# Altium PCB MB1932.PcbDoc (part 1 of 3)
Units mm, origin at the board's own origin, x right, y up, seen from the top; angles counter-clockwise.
Board outline 70 x 82.5 mm, 2 copper layers (Top Layer, Bottom Layer), stack 1.543 mm thick; 185 components, 150 nets, 679 pads, 649 vias.
Unrouted connection lines stored in the file: 108.
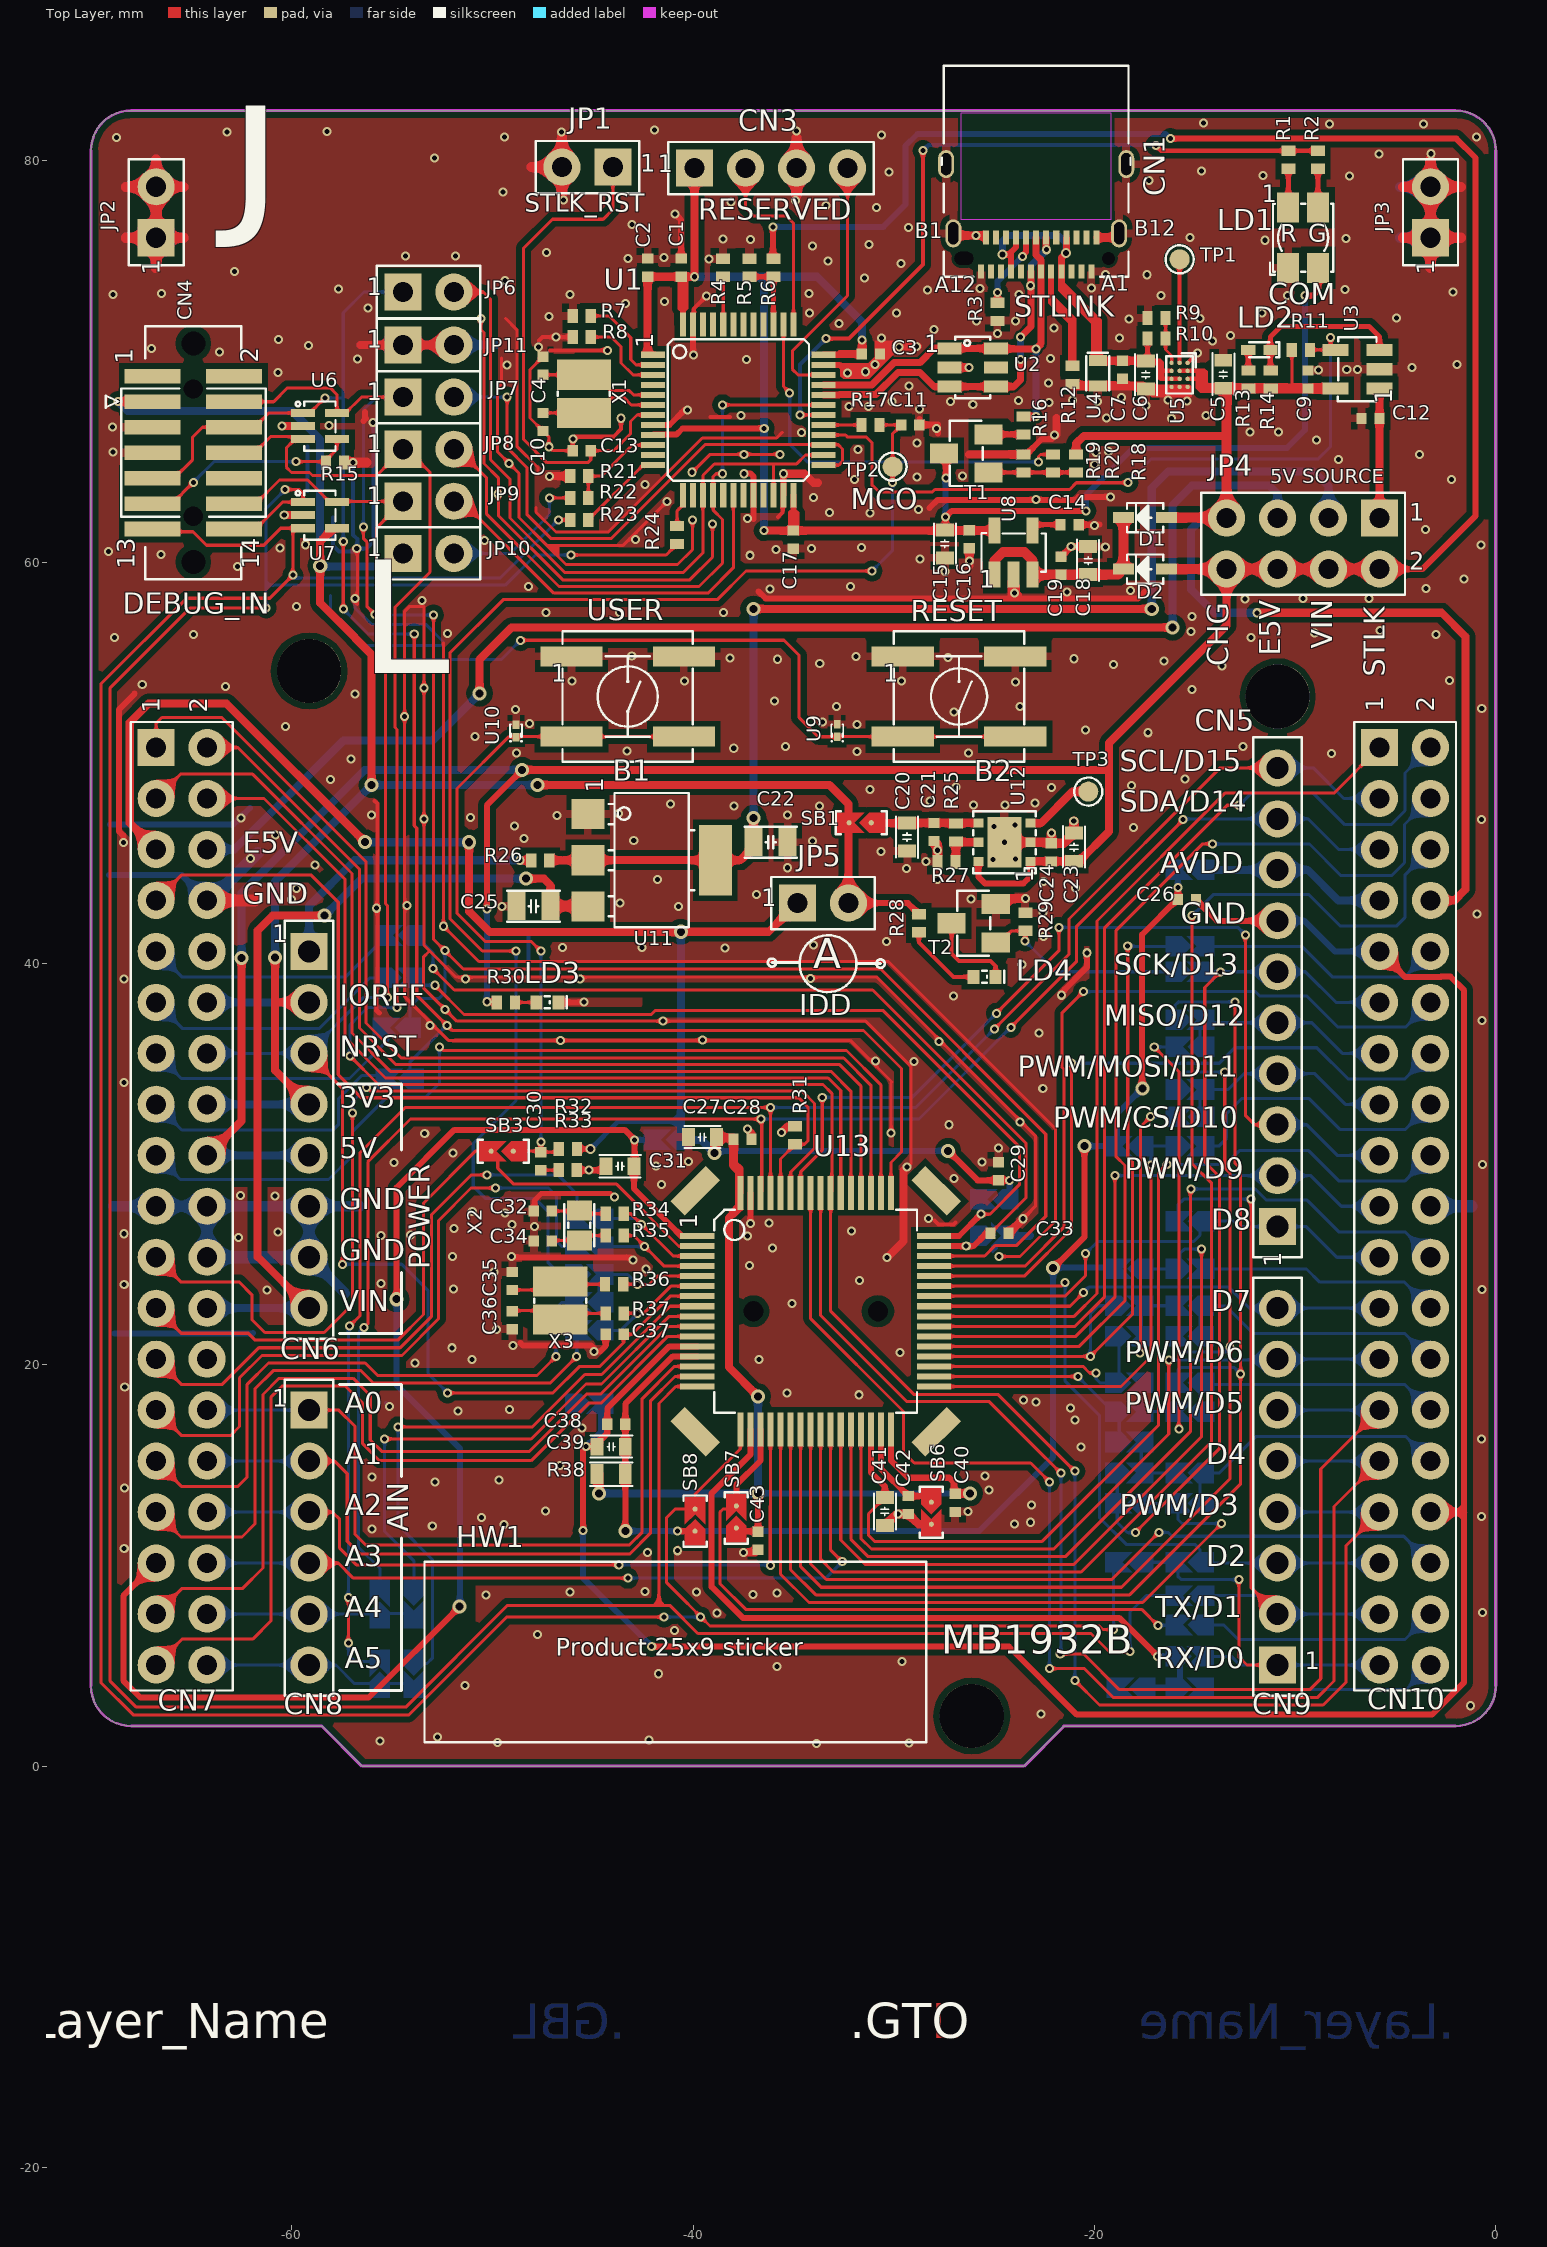
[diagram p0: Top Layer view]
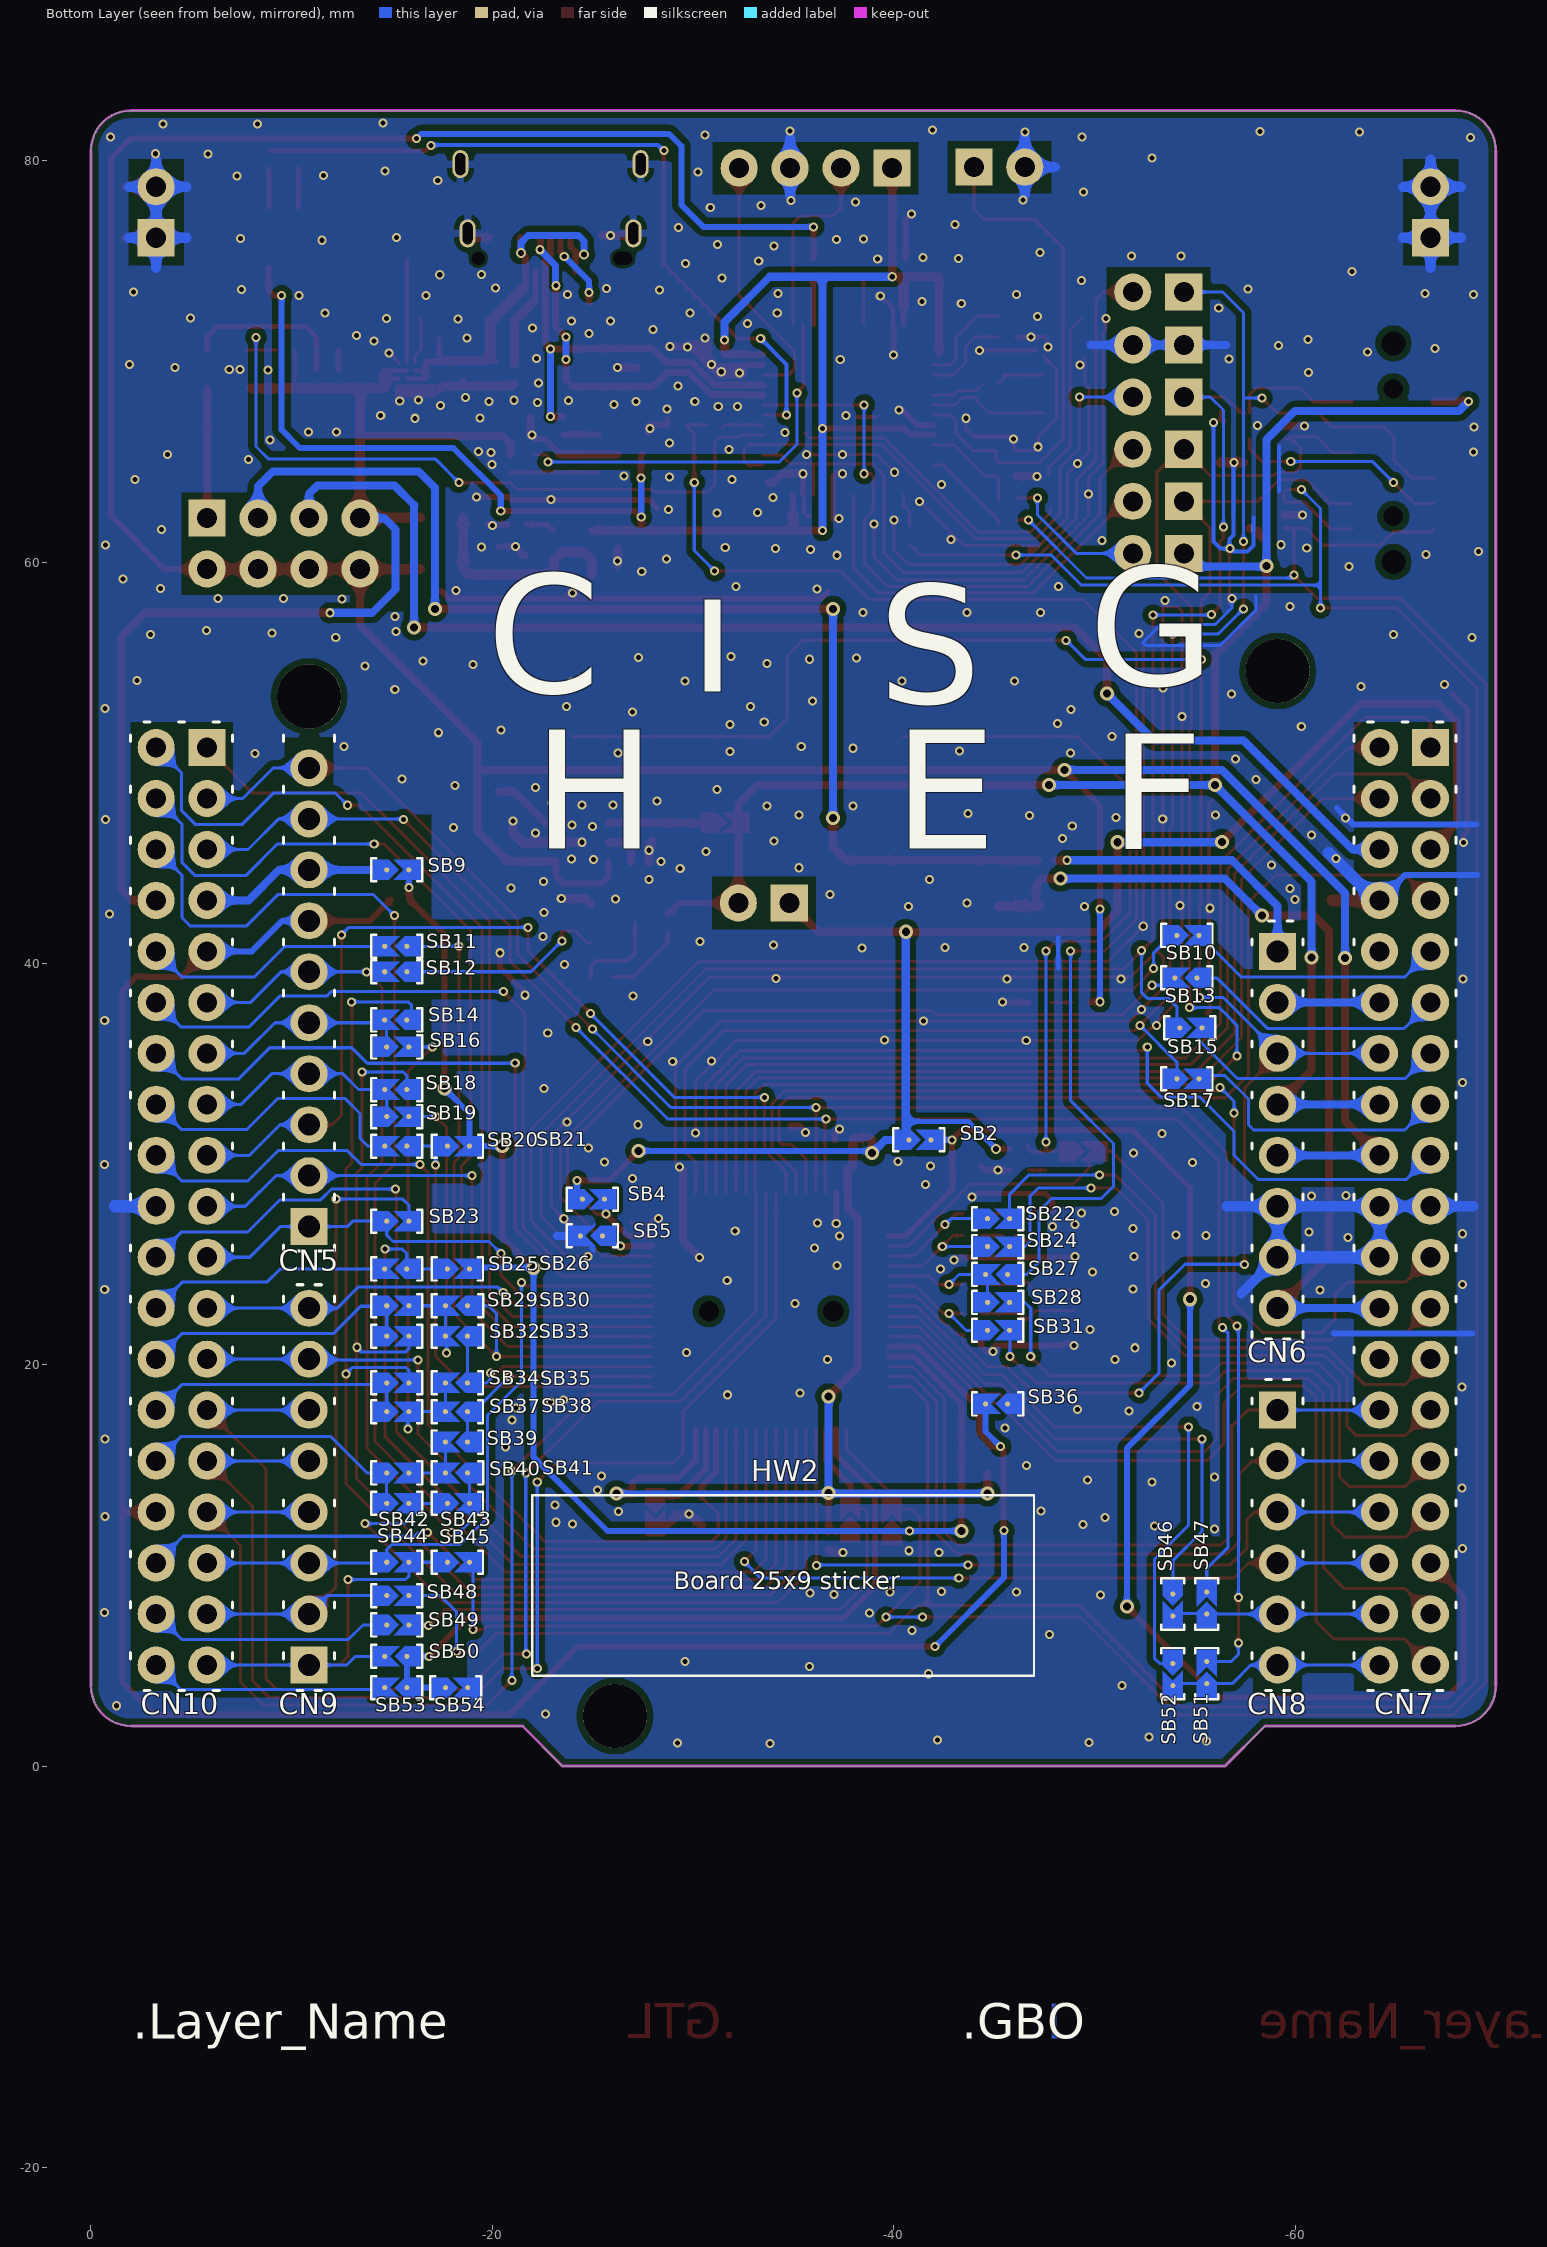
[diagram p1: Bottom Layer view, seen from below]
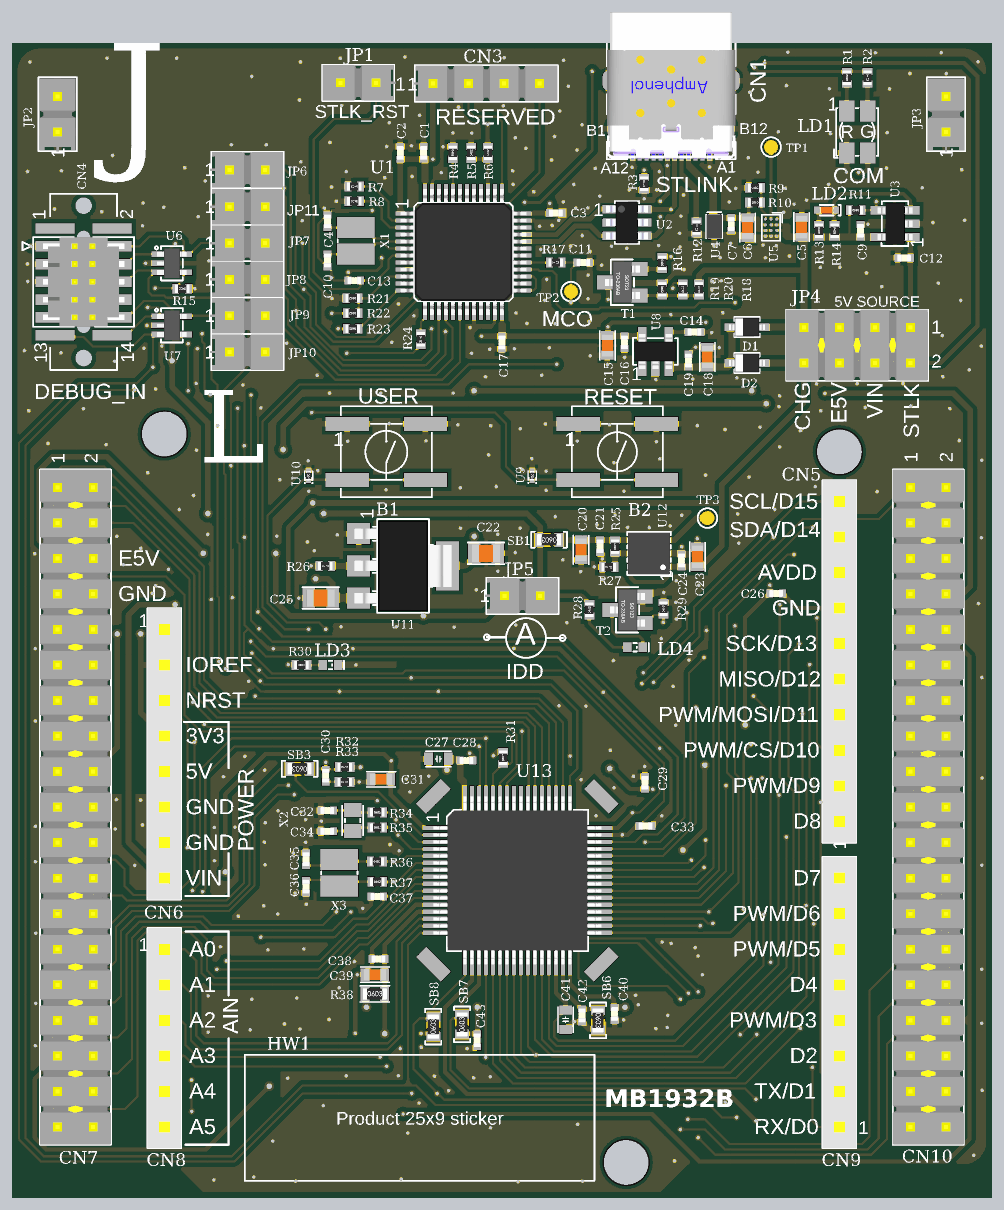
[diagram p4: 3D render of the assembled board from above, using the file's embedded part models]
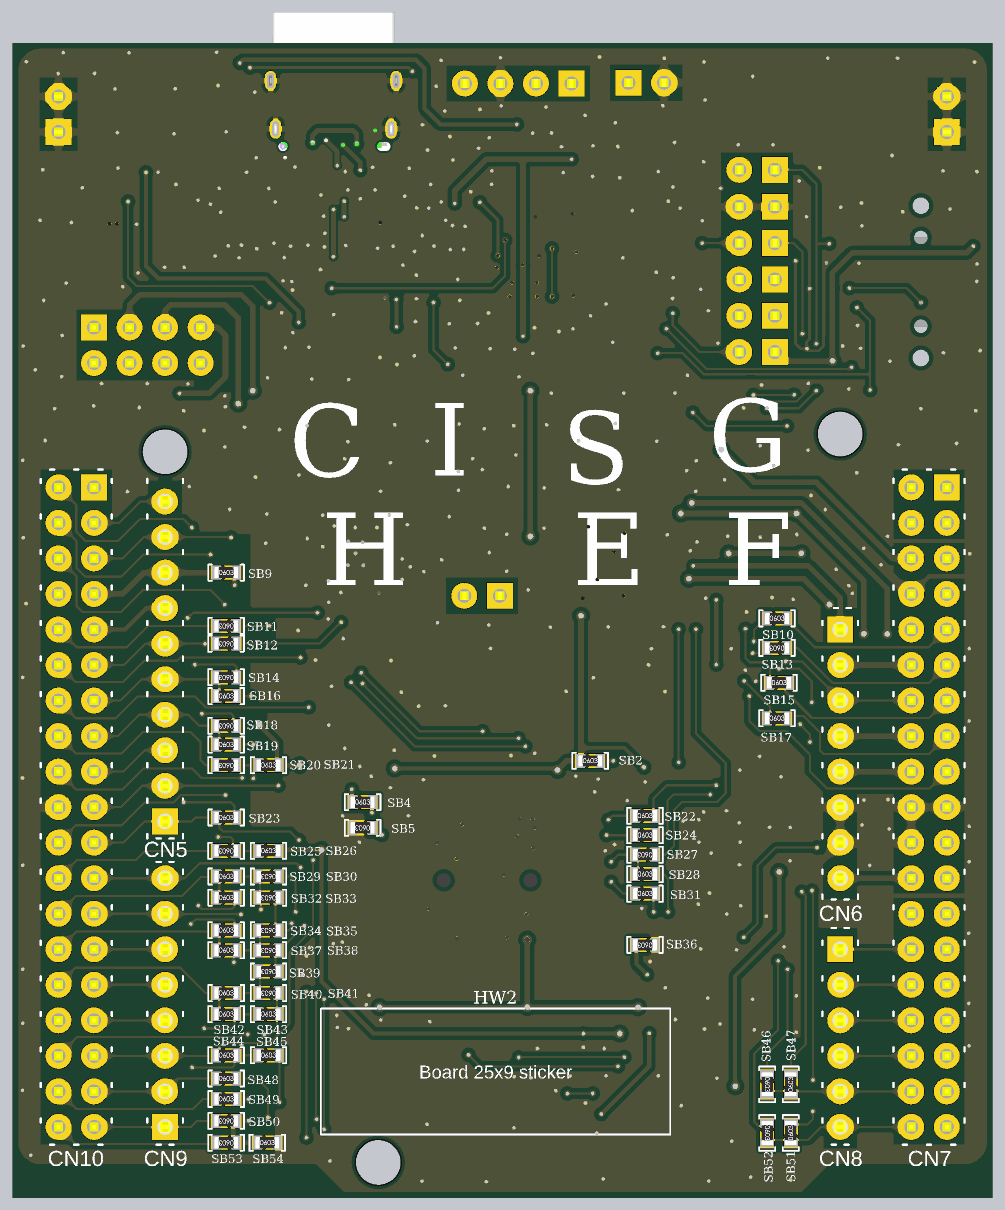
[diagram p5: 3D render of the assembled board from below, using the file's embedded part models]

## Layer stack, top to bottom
Top Solder: solder mask 0.015, Solder Resist, Dk 3.5
Top Layer: signal copper 0.035
Dielectric 1: core 1.4732, FR-4, Dk 4.2
Bottom Layer: signal copper 0.035
Bottom Solder: solder mask 0.015, Solder Resist, Dk 3.5

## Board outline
-68,2 -58.5,2 -56.5,0 -23.5,0 -21.5,2 -21.53,2 -2,2 ccw(c-2,4) 0,4 0,80.5 ccw(c-2,80.5) -2,82.5 -68,82.5 ccw(c-68,80.5) -70,80.5 -70,58 -70,57.974 -70,4 ccw(c-68,4)

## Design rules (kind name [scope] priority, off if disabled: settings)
Clearance USB [InDifferentialPair('STLK_USB')] p1: gap=0.127 ignorepadtopadclearanceinfootprint=FALSE
Clearance IN_CN1 [InComponent('CN1')] p2: gap=0.15 ignorepadtopadclearanceinfootprint=FALSE
Clearance AGND [InNet('AGND') vs InComponent('CN10')] p3: gap=0.14 ignorepadtopadclearanceinfootprint=TRUE
Clearance Polygon [InPolygon] p4: gap=0.3 ignorepadtopadclearanceinfootprint=FALSE
Clearance VIA&VIA [IsVia vs IsVia] p5: gap=0.2 ignorepadtopadclearanceinfootprint=FALSE
Clearance X3 [(HasFootprint('CRY_NX1612SA_4P'))] p6 off: gap=0.127 ignorepadtopadclearanceinfootprint=FALSE
Clearance SB [(HasFootprint('SOLDER-BRIDGE_R0603-0R'))] p7: gap=0.152 ignorepadtopadclearanceinfootprint=FALSE
Clearance U2 [(ObjectKind = 'Pad') And (Component = 'U2') vs (ObjectKind = 'Pad') And (Component = 'U2')] p8 off: gap=0.198 ignorepadtopadclearanceinfootprint=FALSE except(0: Arc-Hole Track-Hole SMDPad-Hole THPad-Hole Via-Hole Fill-Hole Poly-Hole Region-Hole Text-Hole)
Clearance U7 [(ObjectKind = 'Pad') And (Component = 'U7') vs (ObjectKind = 'Pad') And (Component = 'U7')] p9 off: gap=0.198 ignorepadtopadclearanceinfootprint=FALSE except(0: Arc-Hole Track-Hole SMDPad-Hole THPad-Hole Via-Hole Fill-Hole Poly-Hole Region-Hole Text-Hole)
Clearance [All] p10: gap=0.178 ignorepadtopadclearanceinfootprint=FALSE
ComponentClearance [All] p1: gap=0.2 collisioncheckmode=3 verticalgap=0 showdistances=FALSE
DiffPairsRouting [All] p1: maxlimit=0.508 minlimit=0.127 mostfreqgap=0.254 toplayer_minwidth=0.127 toplayer_maxwidth=0.381 toplayer_prefwidth=0.178 bottomlayer_minwidth=0.127 bottomlayer_maxwidth=0.381 bottomlayer_prefwidth=0.178 maxuncoupledlength=12.7
HoleSize [All] p1: absolutevalues=TRUE maxlimit=3.81 minlimit=0.025 maxpercent=80.000 minpercent=20.000
MaxMinImpedance "Schematic Impedance Constraint_2" [InNet('STLK_USB_P')] p1: minimum=85.00 maximum=95.00
MaxMinImpedance "Schematic Impedance Constraint_1" [InNet('STLK_USB_N')] p2: minimum=85.00 maximum=95.00
MinimumSolderMaskSliver [All] p1: minsoldermaskwidth=0
PlaneConnect [All] p1: planeconnectstyle=Relief reliefexpansion=0.508 reliefentries=4 reliefconductorwidth=0.4 reliefairgap=0.254
PolygonConnect VIA [IsVia] p1: connectstyle=Direct reliefconductorwidth=0.254 reliefentries=4 polygonreliefangle="90 Angle" airgapwidth=0.254
PolygonConnect [All] p2: connectstyle=Relief reliefconductorwidth=0.4 reliefentries=4 polygonreliefangle="90 Angle" airgapwidth=0.254
RoutingVias [All] p1: holewidth=0.203 width=0.381 viastyle="Through Hole" minholewidth=0.203 minwidth=0.381 maxholewidth=0.711 maxwidth=1.27
SilkToSilkClearance [All] p1: silktosilkclearance=0
SilkToSolderMaskClearance [IsPad] p1: minsilkscreentomaskgap=0.013 clearancetoexposedcopper=TRUE
SolderMaskExpansion [All] p1: expansion=0.102 istentingtop=FALSE
UnRoutedNet [All] p1: checkbadconnections=TRUE
Width [All] p1: maxlimit=0.762 minlimit=0.127 preferedwidth=0.203
22 further rules are at their usual default settings.

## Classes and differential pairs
net class PF[0..7]: PF0 PF1 PF4 PF5 PF6 PF7
component class U_STLINK_V2EC: C1 C2 C3 C4 C5 C6 C7 C9 C10 C11 C12 C13 C14 C15 C16 C17 C18 C19 CN1 CN3 CN4 D1 D2 JP1 JP6 JP7 JP8 JP9 JP10 JP11 LD1 LD2 R1 R2 R3 R4 R5 R6 R7 R8 R9 R10 R11 R12 R13 R14 R15 R16 R17 R18 R19 R20 R21 R22 R23 R24 T1 TP1 TP2 U1 U2 U3 U4 U5 U6 U7 U8 X1
net class PC[0..15]: PC0 PC1 PC2 PC3 PC4 PC5 PC6 PC7 PC8 PC9 PC10 PC11 PC12 PC13 PC14 PC15
net class PB[0..15]: PB0 PB1 PB2 PB3 PB4 PB5 PB6 PB7 PB8 PB9 PB10 PB11 PB12 PB13 PB14 PB15
net class PA[0..15]: PA0 PA1 PA2 PA3 PA4 PA5 PA6 PA7 PA8 PA9 PA10 PA11 PA12 PA13 PA14 PA15
component class U_Arduino_Morpho_connectors: C26 CN5 CN6 CN7 CN8 CN9 CN10 JP2 JP3 LD4 R26 R28 R29 SB9 SB12 SB14 SB15 SB16 SB17 SB18 SB19 SB22 SB23 SB24 SB28 SB29 SB31 SB32 SB34 SB37 SB40 SB41 SB42 SB43 SB44 SB46 SB47 SB51 SB52 T2
component class U_STM32_microcontroller_IOs: B1 B2 C27 C28 C29 C30 C31 C32 C33 C34 C35 C36 C37 C38 C39 C40 C41 C42 C43 HW6 HW7 HW8 HW9 R31 R32 R33 R34 R35 R36 R37 R38 SB2 SB3 SB4 SB5 SB6 SB7 SB8 SB10 SB11 SB13 SB20 SB21 SB25 SB26 SB27 SB30 SB33 SB35 SB36 SB38 SB39 SB45 SB48 SB49 SB50 SB53 SB54 U9 U10 U13 X2 X3
component class Power: C20 C21 C22 C23 C24 C25 HW12 HW13 JP4 JP5 LD3 R25 R27 R30 SB1 TP3 U11 U12
component class HW_Mechanical_Parts: HW1 HW2
differential pair STLK_USB: +STLK_USB_P -STLK_USB_N

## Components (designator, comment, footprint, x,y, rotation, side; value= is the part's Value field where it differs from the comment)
B1 "SW_BLUE_KSC721JLFS" SWI_C&K_KSC721JLFS_BLUE -43.255,53.3 r0 top locked value=KSC721JLFS
B2 "SW_BLACK_KSC321JLFS" SWI_C&K_KSC321JLFS_BLACK -26.745,53.3 r0 top locked value=KSC321JLFS
C1 "Capacitor" C0402 -40.588,74.672 r90 top value=100nF
C2 "Capacitor" C0402 -42.259,74.672 r90 top value=100nF
C3 "Capacitor" C0402 -31.137,70.37 r0 top value=100nF
C4 "Capacitor" C0402 -47.473,69.782 r270 top value=10pF
C5 "Capacitor" C0603 -13.575,69.357 r270 top value=10uF
C6 "Capacitor" C0603 -17.432,69.325 r270 top value=100nF
C7 "Capacitor" C0402 -18.601,69.581 r270 top value=100pF
C9 "Capacitor" C0402 -9.355,69.098 r270 top value=100nF
C10 "Capacitor" C0402 -47.473,66.982 r270 top value=10pF
C11 "Capacitor" C0402 -29.175,66.833 r180 top value=20pF
C12 "Capacitor" C0402 -6.241,67.158 r0 top value=100nF
C13 "Capacitor" C0402 -45.546,65.548 r0 top value=100nF
C14 "Capacitor" C0402 -21.232,61.862 r180 top value=10nF
C15 "Capacitor" C0603 -27.452,60.905 r90 top value=1uF
C16 "Capacitor" C0402 -26.232,61.133 r90 top value=100nF
C17 "Capacitor" C0402 -35.001,61.117 r270 top value=100nF
C18 "Capacitor" C0603 -20.311,60.073 r270 top value=1uF
C19 "Capacitor" C0402 -21.657,59.819 r270 top value=100nF
C20 "Capacitor" C0603 -29.335,46.297 r90 top value=1uF
C21 "Capacitor" C0402 -27.985,46.549 r90 top value=100nF
C22 "Capacitor" C0805 -36.131,46.043 r180 top value=10uF
C23 "Capacitor" C0603 -21.018,45.793 r270 top value=1uF
C24 "Capacitor" C0402 -22.148,45.534 r270 top value=100nF
C25 "Capacitor" C0805 -47.948,42.853 r0 top value=10uF
C26 "Capacitor" C0402 -15.391,43.181 r180 top value=100nF
C27 "Capacitor" C0603_H0P8 -39.532,31.343 r0 top value=4.7uF
C28 "Capacitor" C0402 -37.533,31.24 r180 top value=100nF
C29 "Capacitor" C0402 -24.777,29.643 r270 top value=100nF
C30 "Capacitor" C0402 -47.591,30.147 r90 top value=100nF
C31 "Capacitor" C0603 -43.64,29.893 r180 top value=1uF
C32 "Capacitor" C0402 -47.485,27.66 r0 top value=8.2pF
C33 "Capacitor" C0402 -24.73,26.55 r0 top value=2.2uF
C34 "Capacitor" C0402 -47.485,26.173 r0 top value=8.2pF
C35 "Capacitor" C0402 -49.004,24.18 r270 top value=10pF
C36 "Capacitor" C0402 -49.003,22.217 r90 top value=10pF
C37 "Capacitor" C0402 -43.901,21.517 r0 top value=100nF
C38 "Capacitor" C0402 -43.822,17.037 r0 top value=100nF
C39 "Capacitor" C0603 -44.076,15.919 r180 top value=1uF
C40 "Capacitor" C0402 -26.938,13.119 r90 top value=100nF
C41 "Capacitor" C0603_H0P8 -30.438,12.693 r270 top value=4.7uF
C42 "Capacitor" C0402 -29.271,13.01 r270 top value=2.2uF
C43 "Capacitor" C0402 -36.76,11.233 r90 top value=100nF
CN1 "USB_TYPE_C_Receptacle" CON_USB-TYPEC_AMPHENOL_12401826E412A -22.9,75.131 r180 top locked value=USB_C_12401826E412A
CN3 "Header 4x1" CON_SAMTEC_TSW-104-07-G-S -36.11,79.63 r0 top
CN4 "Header 7x2" CON_STDC14_Receiver_MEDIUM_WITH_MIPI10_3D -64.896,65.449 r270 top locked value="Header 5x2"
CN5 "Socket 10x1" CON_SAMTEC_SSW-110-01-X-S -10.87,38.314 r90 top locked
CN6 "Socket 8x1" CON_SAMTEC_SSW-108-01-X-S -59.13,31.71 r270 top locked
CN7 "Header 19x2" CON_SAMTEC_TSW-119-09-X-D -65.48,27.9 r270 top locked
CN8 "Socket 6x1" CON_SAMTEC_SSW-106-01-X-S -59.13,11.39 r270 top locked
CN9 "Socket 8x1" CON_SAMTEC_SSW-108-01-X-S -10.87,13.93 r90 top locked
CN10 "Header 19x2" CON_SAMTEC_TSW-119-09-X-D -4.52,27.9 r270 top locked
D1 "BAT60JFILM" DIO_SOD323 -17.474,62.215 r180 top
D2 "BAT60JFILM" DIO_SOD323 -17.474,59.65 r180 top
HW1 "STICKER_PRODUCT" STICKER_PRODUCT_25X9 -40.878,5.692 r0 top value="Sticker product"
HW2 "STICKER_BOARD" STICKER_BOARD_25X9 -34.492,8.999 r180 bottom value="Sticker board"
JP1 "Jumper_Header 2x1" CON_SAMTEC_TSW-102-07-G-S -45.263,79.68 r180 top value="Header 2x1"
JP2 "Jumper_Header 2x1" CON_SAMTEC_TSW-102-09-X-S -66.75,77.43 r90 top locked value="Header 2x1 16mm"
JP3 "Jumper_Header 2x1" CON_SAMTEC_TSW-102-09-X-S -3.25,77.43 r90 top locked value="Header 2x1 16mm"
JP4 "Jumper_Header 4x2 Fitted 1-2" CON_SAMTEC_TSW-104-07-X-D -9.6,60.92 r180 top locked value="Header 4x2"
JP5 "Jumper_Header 2x1 Fitted" CON_SAMTEC_TSW-102-07-G-S -33.528,43.008 r0 top locked value="Header 2x1"
JP6 "Jumper_Header 2x1 Fitted" CON_SAMTEC_TSW-102-07-G-S -53.185,73.458 r0 top value="Header 2x1"
JP7 "Jumper_Header 2x1 Fitted" CON_SAMTEC_TSW-102-07-G-S -53.185,68.217 r0 top value="Header 2x1"
JP8 "Jumper_Header 2x1 Fitted" CON_SAMTEC_TSW-102-07-G-S -53.185,65.621 r0 top value="Header 2x1"
JP9 "Jumper_Header 2x1 Fitted" CON_SAMTEC_TSW-102-07-G-S -53.185,63.028 r0 top value="Header 2x1"
JP10 "Jumper_Header 2x1 Fitted" CON_SAMTEC_TSW-102-07-G-S -53.185,60.432 r0 top value="Header 2x1"
JP11 "Jumper_Header 2x1 Fitted" CON_SAMTEC_TSW-102-07-G-S -53.185,70.818 r0 top value="Header 2x1"
LD1 "LED_BICOLOR" LED_BI-GR_WE-150141SV73110 -9.6,76.16 r0 top locked value="Green / Red"
LD2 "LED_red" LED_0402_KINGBRIGHT_KPHHS-1005SURCK_HYPER-RED_1A2K_H0P5 -11.782,70.571 r0 top value=RED
LD3 "LED_green" "LED_0402_EVERLIGHT_16-213SYGC/S530-E3-TR8 _YELLOW-GREEN_1A2K_H0P45" -47.256,38.06 r180 top locked value="Yellow Green"
LD4 "LED_green" "LED_0402_EVERLIGHT_16-213SYGC/S530-E3-TR8 _YELLOW-GREEN_1A2K_H0P45" -25.475,39.33 r180 top locked value="Yellow Green"
R1 "Resistor" R0402 -10.337,80.046 r90 top value=1K
R2 "Resistor" R0402 -8.863,80.046 r270 top value=330R
R3 "Resistor" R0402 -24.833,72.468 r270 top value=5K1
R4 "Resistor" R0402 -38.506,74.666 r270 top value=100K
R5 "Resistor" R0402 -37.186,74.666 r90 top value=10K
R6 "Resistor" R0402 -35.991,74.666 r90 top value=5K1
R7 "Resistor" R0402 -45.546,72.268 r180 top value=10K
R8 "Resistor" R0402 -45.546,71.212 r180 top value=10K
R9 "Resistor" R0402 -16.902,72.17 r0 top value=180K
R10 "Resistor" R0402 -16.902,71.129 r180 top value=680K
R11 "Resistor" R0402 -9.711,70.571 r180 top value=100K
R12 "Resistor" R0402 -21.087,69.328 r270 top value=5K1
R13 "Resistor" R0402 -12.327,69.098 r270 top value=1K
R14 "Resistor" R0402 -11.212,69.098 r270 top value=100K
R15 "Resistor" R0402 -57.843,64.955 r180 top value=100R
R16 "Resistor" R0402 -23.54,66.8 r270 top value=1K5
R17 "Resistor" R0402 -31.155,66.83 r0 top value=100R
R18 "Resistor" R0402 -20.911,64.91 r90 top value=10K
R19 "Resistor" R0402 -23.54,64.91 r270 top value=36K
R20 "Resistor" R0402 -22.064,64.91 r90 top value=100R
R21 "Resistor" R0402 -45.668,64.278 r180 top value=10K
R22 "Resistor" R0402 -45.668,63.202 r180 top value=10K
R23 "Resistor" R0402 -45.668,62.102 r180 top value=33R
R24 "Resistor" R0402 -40.79,61.35 r270 top value=0R
R25 "Resistor" R0402 -26.905,46.523 r90 top value=47K
R26 "Resistor" R0402 -47.615,45.139 r180 top value=1K
R27 "Resistor" R0402 -27.367,45.055 r0 top value=15K
R28 "Resistor" R0402 -28.742,42.002 r90 top value=680R
R29 "Resistor" R0402 -23.443,42.076 r90 top value=1M
R30 "Resistor" R0402 -49.326,38.06 r0 top value=680R
R31 "Resistor" R0402 -34.91,31.435 r90 top value=100K
R32 "Resistor" R0402 -46.235,30.76 r0 top value=5K1
R33 "Resistor" R0402 -46.24,29.697 r0 top value=100R
R34 "Resistor" R0402 -43.898,27.527 r0 top value=0R
R35 "Resistor" R0402 -43.898,26.441 r0 top value=0R
R36 "Resistor" R0402 -43.93,24.013 r0 top value=0R
R37 "Resistor" R0402 -43.898,22.565 r0 top value=0R
R38 "Resistor" R0603 -44.076,14.548 r0 top value=0R
SB1 "SB_ON" SOLDER-BRIDGE_R0603-0R -31.619,47.008 r180 top
SB2 "SB_ON" SOLDER-BRIDGE_R0603-0R -41.257,31.207 r180 bottom
SB3 "SB_ON" SOLDER-BRIDGE_R0603-0R -49.458,30.642 r180 top
SB4 "SB_ON" SOLDER-BRIDGE_R0603-0R -24.987,28.255 r180 bottom
SB5 "SB_ON" SOLDER-BRIDGE_R0603-0R -24.987,26.422 r0 bottom
SB6 "SB_ON" SOLDER-BRIDGE_R0603-0R -28.123,12.655 r270 top
SB7 "SB_ON" SOLDER-BRIDGE_R0603-0R -37.84,12.368 r90 top
SB8 "SB_OFF" SOLDER-BRIDGE_R0603-0R -39.9,12.21 r90 top
SB9 "SB_ON" SOLDER-BRIDGE_R0603-0R -15.239,44.664 r180 bottom
SB10 "SB_OFF" SOLDER-BRIDGE_R0603-0R -54.61,41.393 r180 bottom
SB11 "SB_OFF" SOLDER-BRIDGE_R0603-0R -15.239,40.854 r0 bottom
SB12 "SB_ON" SOLDER-BRIDGE_R0603-0R -15.24,39.584 r0 bottom
SB13 "SB_OFF" SOLDER-BRIDGE_R0603-0R -54.609,39.279 r0 bottom
SB14 "SB_ON" SOLDER-BRIDGE_R0603-0R -15.237,37.184 r0 bottom
SB15 "SB_OFF" SOLDER-BRIDGE_R0603-0R -54.758,36.79 r180 bottom
SB16 "SB_OFF" SOLDER-BRIDGE_R0603-0R -15.237,35.837 r180 bottom
SB17 "SB_OFF" SOLDER-BRIDGE_R0603-0R -54.609,34.25 r180 bottom
SB18 "SB_ON" SOLDER-BRIDGE_R0603-0R -15.239,33.717 r0 bottom
SB19 "SB_OFF" SOLDER-BRIDGE_R0603-0R -15.239,32.37 r180 bottom
SB20 "SB_ON" SOLDER-BRIDGE_R0603-0R -15.239,30.897 r0 bottom
SB21 "SB_OFF" SOLDER-BRIDGE_R0603-0R -18.261,30.897 r180 bottom
SB22 "SB_OFF" SOLDER-BRIDGE_R0603-0R -45.176,27.283 r180 bottom
SB23 "SB_OFF" SOLDER-BRIDGE_R0603-0R -15.239,27.156 r180 bottom
SB24 "SB_OFF" SOLDER-BRIDGE_R0603-0R -45.176,25.891 r180 bottom
SB25 "SB_ON" SOLDER-BRIDGE_R0603-0R -15.236,24.776 r0 bottom
SB26 "SB_OFF" SOLDER-BRIDGE_R0603-0R -18.259,24.776 r180 bottom
SB27 "SB_ON" SOLDER-BRIDGE_R0603-0R -45.176,24.5 r0 bottom
SB28 "SB_ON" SOLDER-BRIDGE_R0603-0R -45.176,23.108 r180 bottom
SB29 "SB_ON" SOLDER-BRIDGE_R0603-0R -15.241,22.942 r180 bottom
SB30 "SB_ON" SOLDER-BRIDGE_R0603-0R -18.263,22.942 r0 bottom
SB31 "SB_ON" SOLDER-BRIDGE_R0603-0R -45.176,21.717 r180 bottom
SB32 "SB_OFF" SOLDER-BRIDGE_R0603-0R -15.241,21.429 r180 bottom
SB33 "SB_OFF" SOLDER-BRIDGE_R0603-0R -18.263,21.429 r0 bottom
SB34 "SB_OFF" SOLDER-BRIDGE_R0603-0R -15.239,19.098 r180 bottom
SB35 "SB_ON" SOLDER-BRIDGE_R0603-0R -18.262,19.098 r0 bottom
SB36 "SB_ON" SOLDER-BRIDGE_R0603-0R -45.176,18.05 r0 bottom
SB37 "SB_ON" SOLDER-BRIDGE_R0603-0R -15.239,17.666 r180 bottom
SB38 "SB_OFF" SOLDER-BRIDGE_R0603-0R -18.262,17.666 r0 bottom
SB39 "SB_ON" SOLDER-BRIDGE_R0603-0R -18.262,16.153 r0 bottom
SB40 "SB_ON" SOLDER-BRIDGE_R0603-0R -15.241,14.61 r180 bottom
SB41 "SB_OFF" SOLDER-BRIDGE_R0603-0R -18.263,14.61 r0 bottom
SB42 "SB_OFF" SOLDER-BRIDGE_R0603-0R -15.238,13.097 r180 bottom
SB43 "SB_ON" SOLDER-BRIDGE_R0603-0R -18.261,13.097 r180 bottom
SB44 "SB_OFF" SOLDER-BRIDGE_R0603-0R -15.24,10.16 r180 bottom
SB45 "SB_OFF" SOLDER-BRIDGE_R0603-0R -18.263,10.16 r180 bottom
SB46 "SB_ON" SOLDER-BRIDGE_R0603-0R -53.909,8.083 r270 bottom
SB47 "SB_OFF" SOLDER-BRIDGE_R0603-0R -55.599,8.083 r90 bottom
SB48 "SB_OFF" SOLDER-BRIDGE_R0603-0R -15.239,8.499 r180 bottom
SB49 "SB_OFF" SOLDER-BRIDGE_R0603-0R -15.24,7.036 r180 bottom
SB50 "SB_OFF" SOLDER-BRIDGE_R0603-0R -15.24,5.474 r0 bottom
SB51 "SB_OFF" SOLDER-BRIDGE_R0603-0R -55.599,4.612 r90 bottom
SB52 "SB_ON" SOLDER-BRIDGE_R0603-0R -53.909,4.612 r270 bottom
SB53 "SB_OFF" SOLDER-BRIDGE_R0603-0R -15.24,3.912 r0 bottom
SB54 "SB_ON" SOLDER-BRIDGE_R0603-0R -18.173,3.912 r180 bottom
T1 "9013-SOT23" NPN_SOT23 -26.384,65.416 r90 top value="NPN SOT23"
T2 "BSN20" MOS_SOT23 -26.014,42.002 r90 top value=BSN20BK
TP1 "Test Point" TP_SMD_1MM -15.753,75.082 r180 top
TP2 "Test Point" TP_SMD_1MM -30.055,64.75 r90 top
TP3 "Test Point" TP_SMD_1MM -20.304,48.563 r180 top
U1 "STLINK-V2EC" ICC_LQFP48_7X7_P050 -37.743,67.58 r270 top locked value=STM32F103CBT6
U2 "USBLC6-2SC6" ESD_SOT23-6L -26.06,69.693 r270 top
U3 "STMPS2141STR" MOS_SOT23-5L -6.891,69.606 r90 top
U4 "ESD-TRANSIL" ESD_QFN1610_2N_1K_2A -19.825,69.408 r270 top value=ESDA25P35-1U1M
U5 "FPF3380UCX" ICC_WLCSP12_1P858x1P318_P040 -15.753,69.326 r270 top
U6 "ESDALC6V1W5" ESD_SOT323-5L -58.588,66.777 r270 top
U7 "ESDALC6V1W5" ESD_SOT323-5L -58.588,62.334 r270 top locked
U8 "LDK120M33R" REG_SOT23-5L -24.023,60.473 r0 top
U9 "ESD-TRANSIL" ESD_ST0201 -32.821,51.598 r90 top value=ESDALC6V1-1U2
U10 "ESD-TRANSIL" ESD_ST0201 -48.819,51.587 r90 top value=ESDALC6V1-1U2
U11 "LD1117S50TR" REG_SOT223-TAB -42.062,45.144 r270 top
U12 "LD39100PUR" ICC_DFN6-EPAD_3X3_P095 -24.48,46.038 r90 top
U13 "STM32_MCU_LQFP64" ICC_LQFP64_10X10_P050_SOCKET_YAMAICHI_IC149-064-069-B5_NM -33.888,22.668 r270 top locked value=STM32U083RCT6
X1 "XTAL_2_PINS" CRY_NX3225GD_2P -45.439,68.382 r90 top value=8MHz
X2 "XTAL_2_PINS" CRY_NX2012SA_2P -45.665,26.947 r90 top value=32.768KHz
X3 "XTAL_2_PINS" CRY_NX3225GD_2P -46.615,23.2 r90 top value=8MHz

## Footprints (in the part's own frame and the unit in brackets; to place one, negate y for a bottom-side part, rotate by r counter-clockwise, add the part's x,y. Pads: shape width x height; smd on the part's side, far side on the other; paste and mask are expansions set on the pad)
C0402 [mm]
  rect 0.51x0.56 smd mask+0.05: 1(-0.45,0) 2(0.45,0)
  body extent -0.5,-0.3 0.5,0.3, height 0.4
C0603 [mm]
  rect 0.64x0.89 smd mask+0.05: 1(-0.7,0) 2(0.7,0)
  silkscreen extent -1.05,-0.55 1.02,0.55, body extent -0.9,-0.5 0.9,0.5, height 1.4
C0603_H0P8 [mm] "MCD-01540"
  rect 0.64x0.89 smd mask+0.05: 1(-0.7,0) 2(0.7,0)
  silkscreen extent -0.9,-0.55 0.9,0.55, body extent -0.9,-0.5 0.9,0.5, height 1
C0805 [mm]
  rect 0.9x1.4 smd mask+0.05: 1(-0.85,0) 2(0.85,0)
  silkscreen extent -1.3,-0.77 1.3,0.77, body extent -1.1,-0.7 1.1,0.7, height 1.35
CON_SAMTEC_SSW-106-01-X-S [mm] "MCD-02079"
  rect 1.85x1.85 / inner round 1.85 / far side rect 1.85x1.85 hole 1.1 mask+0.05: 1(-6.35,0)
  round 1.85 hole 1.1 mask+0.05: 2(-3.81,0) 3(-1.27,0) 4(1.27,0) 5(3.81,0) 6(6.35,0)
  silkscreen extent -7.88,-1.2 7.88,1.2, body extent -7.88,-1.21 7.88,1.21, height 8.51
CON_SAMTEC_SSW-108-01-X-S [mm] "MCD-01743"
  rect 1.85x1.85 / inner round 1.85 / far side rect 1.85x1.85 hole 1.1 mask+0.05: 1(-8.89,0)
  round 1.85 hole 1.1 mask+0.05: 2(-6.35,0) 3(-3.81,0) 4(-1.27,0) 5(1.27,0) 6(3.81,0) 7(6.35,0) 8(8.89,0)
  silkscreen extent -10.42,-1.2 10.42,1.2, body extent -10.42,-1.21 10.42,1.21, height 8.51
CON_SAMTEC_SSW-110-01-X-S [mm] "MCD-02080"
  rect 1.85x1.85 / inner round 1.85 / far side rect 1.85x1.85 hole 1.1 mask+0.05: 1(-11.43,0)
  round 1.85 hole 1.1 mask+0.05: 2(-8.89,0) 3(-6.35,0) 4(-3.81,0) 5(-1.27,0) 6(1.27,0) 7(3.81,0) 8(6.35,0) 9(8.89,0) 10(11.43,0)
  silkscreen extent -12.96,-1.2 12.96,1.2, body extent -12.96,-1.21 12.96,1.21, height 8.51
CON_SAMTEC_TSW-102-07-G-S [mm]
  rect 1.85x1.85 / inner round 1.85 / far side rect 1.85x1.85 hole 1 mask+0.05: 1(-1.27,0)
  round 1.85 hole 1 mask+0.05: 2(1.27,0)
  silkscreen extent -2.58,-1.3 2.58,1.3, body extent -2.67,-1.3 2.58,1.3, height 8.38
CON_SAMTEC_TSW-102-09-X-S [mm]
  rect 1.85x1.85 / inner round 1.85 / far side rect 1.85x1.85 hole 1 mask+0.05: 1(-1.27,0)
  round 1.85 hole 1 mask+0.05: 2(1.27,0)
  silkscreen extent -2.64,-1.37 2.64,1.37, body extent -2.67,-1.3 2.58,1.3, height 8.38
CON_SAMTEC_TSW-104-07-G-S [mm]
  rect 1.85x1.85 / inner round 1.85 / far side rect 1.85x1.85 hole 1 mask+0.05: 1(-3.81,0)
  round 1.85 hole 1 mask+0.05: 2(-1.27,0) 3(1.27,0) 4(3.81,0)
  silkscreen extent -5.12,-1.3 5.12,1.3, body extent -5.21,-1.37 5.18,1.37, height 8.38
CON_SAMTEC_TSW-104-07-X-D [mm]
  rect 1.85x1.85 / inner round 1.85 / far side rect 1.85x1.85 hole 1 mask+0.05: 1(-3.81,-1.27)
  round 1.85 hole 1 mask+0.05: 2(-3.81,1.27) 3(-1.27,-1.27) 4(-1.27,1.27) 5(1.27,-1.27) 6(1.27,1.27) 7(3.81,-1.27) 8(3.81,1.27)
  silkscreen extent -5.08,-2.54 5.08,2.54, body extent -5.08,-2.54 5.08,2.54, height 8.38
CON_SAMTEC_TSW-119-09-X-D [mm]
  rect 1.85x1.85 / inner round 1.85 / far side rect 1.85x1.85 hole 1 mask+0.05: 1(-22.86,-1.27)
  round 1.85 hole 1 mask+0.05: 2(-22.86,1.27) 3(-20.32,-1.27) 4(-20.32,1.27) 5(-17.78,-1.27) 6(-17.78,1.27) 7(-15.24,-1.27) 8(-15.24,1.27) 9(-12.7,-1.27) 10(-12.7,1.27) 11(-10.16,-1.27) 12(-10.16,1.27) 13(-7.62,-1.27) 14(-7.62,1.27) 15(-5.08,-1.27) 16(-5.08,1.27) 17(-2.54,-1.27) 18(-2.54,1.27) 19(0,-1.27) 20(0,1.27) 21(2.54,-1.27) 22(2.54,1.27) 23(5.08,-1.27) 24(5.08,1.27) 25(7.62,-1.27) 26(7.62,1.27) 27(10.16,-1.27) 28(10.16,1.27) 29(12.7,-1.27) 30(12.7,1.27) 31(15.24,-1.27) 32(15.24,1.27) 33(17.78,-1.27) 34(17.78,1.27) 35(20.32,-1.27) 36(20.32,1.27) 37(22.86,-1.27) 38(22.86,1.27)
  silkscreen extent -24.13,-2.54 24.13,2.54, body extent -24.13,-2.55 24.13,2.54, height 8.38
CON_STDC14_Receiver_MEDIUM_WITH_MIPI10_3D [mm] "compatible with FTSH-105-01-L-DV,-K and FTSH-107-01-L-DV,-K,-A,-P,-ES"
  round 0 hole 1.19 unplated mask+0.05: 0(-5.445,0) 0(5.445,0)
  round 0 hole 0.97 unplated mask+0.05: 0(-3.175,0) 0(3.175,0)
  rect 0.74x2.79 smd mask+0.05: 1(-3.81,-2.032) 2(-3.81,2.032) 3(-2.54,-2.032) 4(-2.54,2.032) 5(-1.27,-2.032) 6(-1.27,2.032) 7(0,-2.032) 8(0,2.032) 9(1.27,-2.032) 10(1.27,2.032) 11(2.54,-2.032) 12(2.54,2.032) 13(3.81,-2.032) 14(3.81,2.032)
  silkscreen extent -6.3,-4.38 6.3,3.6, body extent -6.3,-2.92 6.3,2.92, height 6.6
CON_USB-TYPEC_AMPHENOL_12401826E412A [mm] "MCD-03232"
  round 0 hole 0.65 unplated mask+0.05: 0(-3.6,0)
  round 0 hole 0.65 slot 0.95 at 0 deg unplated mask+0.05: 0(3.6,0)
  rect 0.3x0.7 smd mask+0.05: A1(-2.75,0.66) A2(-2.25,0.66) A3(-1.75,0.66) A4(-1.25,0.66) A5(-0.75,0.66) A6(-0.25,0.66) A7(0.25,0.66) A8(0.75,0.66) A9(1.25,0.66) A10(1.75,0.66) A11(2.25,0.66) A12(2.75,0.66) B1(2.5,-1.04) B2(2,-1.04) B3(1.5,-1.04) B4(1,-1.04) B5(0.5,-1.04) B6(0,-1.04) B7(-0.5,-1.04) B8(-1,-1.04) B9(-1.5,-1.04) B10(-2,-1.04) B11(-2.5,-1.04) B12(-3,-1.04)
  oval 0.8x1.4 hole 0.5 slot 1.1 at 90 deg mask+0.05: SH1(-4.13,-1.25) SH2(4.13,-1.25) SH3(-4.49,-4.7) SH4(4.49,-4.7)
  Top Layer keep-out region: -3.75,-7.24 3.75,-7.24 3.75,-1.95 -3.75,-1.95
  silkscreen extent -4.7,-9.59 4.7,0.91, body extent -4.6,-9.59 4.6,0.91, height 3.25
CRY_NX2012SA_2P [mm]
  rect 1x1.25 smd mask+0.05: 1(-0.75,0) 2(0.75,0)
  silkscreen extent -1.05,-0.75 1.05,0.75, body extent -1.05,-0.63 1.05,0.63, height 0.6
CRY_NX3225GD_2P [mm]
  rect 1.5x2.7 smd mask+0.05: 1(-0.95,0) 2(0.95,0)
  silkscreen extent -0.1,-1.3 0.1,1.3, body extent -1.65,-1.3 1.65,1.3, height 1
DIO_SOD323 [mm]
  rect 1.06x0.54 smd mask+0.05: 1(-1.07,0) 2(1.07,0)
  silkscreen extent -0.9,-0.72 0.9,0.72, body extent -1.3,-0.78 1.3,0.78, height 1.17
ESD_QFN1610_2N_1K_2A [mm] "DFN, 2-Leads, Body 1.60x1.00mm"
  rect 0.55x0.9 smd mask+0.05: 1(-0.625,0) 2(0.625,0)
  silkscreen extent -1.02,-0.58 0.85,0.58, body extent -0.85,-0.55 0.85,0.55, height 0.6
ESD_SOT23-6L [mm]
  rect 0.6x1.2 smd mask+0.05: 1(-0.95,-1.15) 2(0,-1.15) 3(0.95,-1.15) 4(0.95,1.15) 5(0,1.15) 6(-0.95,1.15)
  silkscreen extent -1.53,-0.87 1.53,0.87, body extent -1.52,-1.5 1.52,1.5, height 1.45
ESD_SOT323-5L [mm]
  rect 0.4x1.2 smd mask+0.05: 1(-0.65,-0.85) 2(0,-0.85) 3(0.65,-0.85) 4(0.65,0.85) 5(-0.65,0.85)
  silkscreen extent -1.22,-1.21 1.22,0.77, body extent -1.15,-1.05 1.15,1.05, height 1.1
ESD_ST0201 [mm]
  rect 0.425x0.33 smd mask+0.05: 1(-0.312,0) 2(0.312,0)
  silkscreen extent -0.55,-0.3 0.33,0.3, body extent -0.34,-0.18 0.34,0.18, height 0.34
ICC_DFN6-EPAD_3X3_P095 [mm]
  rect 0.45x0.5 smd mask+0.05: 1(-0.95,-1.3) 2(0,-1.3) 3(0.95,-1.3) 4(0.95,1.3) 5(0,1.3) 6(-0.95,1.3)
  rect 2.5x1.7 smd mask+0.05: EP(0,0)
  silkscreen extent -1.55,-1.55 1.55,1.55, body extent -1.55,-1.55 1.55,1.55, height 1
ICC_LQFP48_7X7_P050 [mm]
  rect 0.3x1.2 smd mask+0.05: 1(-2.75,-4.25) 2(-2.25,-4.25) 3(-1.75,-4.25) 4(-1.25,-4.25) 5(-0.75,-4.25) 6(-0.25,-4.25) 7(0.25,-4.25) 8(0.75,-4.25) 9(1.25,-4.25) 10(1.75,-4.25) 11(2.25,-4.25) 12(2.75,-4.25) 25(2.75,4.25) 26(2.25,4.25) 27(1.75,4.25) 28(1.25,4.25) 29(0.75,4.25) 30(0.25,4.25) 31(-0.25,4.25) 32(-0.75,4.25) 33(-1.25,4.25) 34(-1.75,4.25) 35(-2.25,4.25) 36(-2.75,4.25)
  rect 1.2x0.3 smd mask+0.05: 13(4.25,-2.75) 14(4.25,-2.25) 15(4.25,-1.75) 16(4.25,-1.25) 17(4.25,-0.75) 18(4.25,-0.25) 19(4.25,0.25) 20(4.25,0.75) 21(4.25,1.25) 22(4.25,1.75) 23(4.25,2.25) 24(4.25,2.75) 37(-4.25,2.75) 38(-4.25,2.25) 39(-4.25,1.75) 40(-4.25,1.25) 41(-4.25,0.75) 42(-4.25,0.25) 43(-4.25,-0.25) 44(-4.25,-0.75) 45(-4.25,-1.25) 46(-4.25,-1.75) 47(-4.25,-2.25) 48(-4.25,-2.75)
  silkscreen extent -3.52,-3.52 3.52,3.52, body extent -4.5,-4.5 4.5,4.5, height 1.6
ICC_LQFP64_10X10_P050_SOCKET_YAMAICHI_IC149-064-069-B5_NM [mm]
  rect 1x2.5 smd rot 135 mask+0.05: 0(-6,6) 0(6,-6)
  rect 1x2.5 smd rot 45 mask+0.05: 0(-6,-6) 0(6,6)
  round 0.5 hole 1 unplated mask+0.05: 0(0,3.1) 0(0,-3.1)
  rect 0.3x1.7 smd mask+0.05: 1(-3.75,-5.9) 2(-3.25,-5.9) 3(-2.75,-5.9) 4(-2.25,-5.9) 5(-1.75,-5.9) 6(-1.25,-5.9) 7(-0.75,-5.9) 8(-0.25,-5.9) 9(0.25,-5.9) 10(0.75,-5.9) 11(1.25,-5.9) 12(1.75,-5.9) 13(2.25,-5.9) 14(2.75,-5.9) 15(3.25,-5.9) 16(3.75,-5.9) 33(3.75,5.9) 34(3.25,5.9) 35(2.75,5.9) 36(2.25,5.9) 37(1.75,5.9) 38(1.25,5.9) 39(0.75,5.9) 40(0.25,5.9) 41(-0.25,5.9) 42(-0.75,5.9) 43(-1.25,5.9) 44(-1.75,5.9) 45(-2.25,5.9) 46(-2.75,5.9) 47(-3.25,5.9) 48(-3.75,5.9)
  rect 1.7x0.3 smd mask+0.05: 17(5.9,-3.75) 18(5.9,-3.25) 19(5.9,-2.75) 20(5.9,-2.25) 21(5.9,-1.75) 22(5.9,-1.25) 23(5.9,-0.75) 24(5.9,-0.25) 25(5.9,0.25) 26(5.9,0.75) 27(5.9,1.25) 28(5.9,1.75) 29(5.9,2.25) 30(5.9,2.75) 31(5.9,3.25) 32(5.9,3.75) 49(-5.9,3.75) 50(-5.9,3.25) 51(-5.9,2.75) 52(-5.9,2.25) 53(-5.9,1.75) 54(-5.9,1.25) 55(-5.9,0.75) 56(-5.9,0.25) 57(-5.9,-0.25) 58(-5.9,-0.75) 59(-5.9,-1.25) 60(-5.9,-1.75) 61(-5.9,-2.25) 62(-5.9,-2.75) 63(-5.9,-3.25) 64(-5.9,-3.75)
  silkscreen extent -5.05,-5.05 5.05,5.05, body extent -6,-6 6,6, height 1.6
ICC_WLCSP12_1P858x1P318_P040 [mm] "MCD-03166"
  round 0.215 smd paste+0 mask+0.04: A1(-0.6,0.4) A2(-0.2,0.4) A3(0.2,0.4) A4(0.6,0.4) B1(-0.6,0) B2(-0.2,0) B3(0.2,0) B4(0.6,0) C1(-0.6,-0.4) C2(-0.2,-0.4) C3(0.2,-0.4) C4(0.6,-0.4)
  silkscreen extent -1.07,-0.66 0.93,0.8, body extent -0.93,-0.66 0.93,0.66, height 0.62
"LED_0402_EVERLIGHT_16-213SYGC/S530-E3-TR8 _YELLOW-GREEN_1A2K_H0P45" [mm] "MCD-02330"
  rect 0.6x0.7 smd mask+0.05: 1(0.55,0) 2(-0.55,0)
  silkscreen extent -0.97,-0.3 0.13,0.3, body extent -0.55,-0.3 0.55,0.3, height 0.55
LED_0402_KINGBRIGHT_KPHHS-1005SURCK_HYPER-RED_1A2K_H0P5 [mm] "MCD-00708"
  rect 0.7x0.5 smd mask+0.05: 1(-0.55,0) 2(0.55,0)
  silkscreen extent -0.5,-0.38 1,0.38, body extent -0.5,-0.3 0.51,0.3, height 0.6
LED_BI-GR_WE-150141SV73110 [mm] "MCD-02631"
  rect 1.1x1.5 smd mask+0.05: 1(-0.75,1.5) 2(0.75,1.5) 3(-0.75,-1.5) 4(0.75,-1.5)
  silkscreen extent -1.65,-1.85 1.5,1.7, body extent -1.5,-1.85 1.5,1.85, height 2.1
MOS_SOT23 [mm]
  rect 1x1.4 smd mask+0.05: 1(-0.95,-1.1) 2(0.95,-1.1) 3(0,1.1)
  silkscreen extent -1.63,-0.82 1.63,0.82, body extent -1.56,-1.25 1.56,1.25, height 1.1
MOS_SOT23-5L [mm]
  rect 0.6x1.3 smd mask+0.05: 1(-0.95,-1.1) 2(0,-1.1) 3(0.95,-1.1) 4(0.95,1.1) 5(-0.95,1.1)
  silkscreen extent -1.6,-0.95 1.6,0.97, body extent -1.52,-1.25 1.52,1.25, height 1.45
NPN_SOT23 [mm]
  rect 1x1.4 smd mask+0.05: 1(-0.95,-1.1) 2(0.95,-1.1) 3(0,1.1)
  silkscreen extent -1.63,-0.82 1.63,0.82, body extent -1.56,-1.25 1.56,1.25, height 1.1
R0402 [mm]
  rect 0.51x0.7 smd mask+0.05: 1(-0.45,0) 2(0.45,0)
  body extent -0.52,-0.3 0.52,0.3, height 0.4
R0603 [mm]
  rect 0.64x1 smd mask+0.05: 1(-0.7,0) 2(0.7,0)
  silkscreen extent -1.05,-0.58 1.05,0.58, body extent -0.9,-0.5 0.9,0.5, height 0.56
REG_SOT23-5L [mm]
  rect 0.6x1.3 smd mask+0.05: 1(-0.95,-1.1) 2(0,-1.1) 3(0.95,-1.1) 4(0.95,1.1) 5(-0.95,1.1)
  silkscreen extent -1.6,-0.95 1.6,0.97, body extent -1.52,-1.25 1.52,1.25, height 1.1
REG_SOT223-TAB [mm]
  rect 1.5x1.65 smd mask+0.05: 1(-2.3,-3.175) 2(0,-3.175) 3(2.3,-3.175)
  rect 3.5x1.65 smd mask+0.05: 4(0,3.175)
  silkscreen extent -3.35,-2.15 3.35,2.12, body extent -3.35,-3.48 3.35,3.48, height 1.8
SOLDER-BRIDGE_R0603-0R [mil]
  round 10 smd paste-393.7: 1(-19.68,0) 2(23.62,0)
  Top Layer region: -5.91,19.69 13.78,0 -5.91,-19.68 47.24,-19.68 47.24,19.69 -5.91,19.69
  Top Layer region: -47.24,-19.68 -47.24,19.69 -15.75,19.69 3.94,0 -15.75,-19.68 -47.24,-19.68
  silkscreen extent -50,-23 50,23, body extent -36,-20 36,20, height 22
STICKER_BOARD_25X9 [mm] "Sticker to mention board CPN code"
  silkscreen extent -12.5,-4.5 12.5,4.5
STICKER_PRODUCT_25X9 [mm] "Sticker to mention board CPN code"
  silkscreen extent -12.5,-4.5 12.5,4.5
SWI_C&K_KSC321JLFS_BLACK [mm] "MCD-01799"
  rect 3.1x1 smd mask+0.05: 1(-2.8,2) 2(2.8,2) 3(-2.8,-2) 4(2.8,-2)
  silkscreen extent -3.25,-3.25 3.25,3.25, body extent -3.4,-3.25 3.4,3.25, height 3.5
SWI_C&K_KSC721JLFS_BLUE [mm] "MCD-01800"
  rect 3.1x1 smd mask+0.05: 1(-2.8,2) 2(2.8,2) 3(-2.8,-2) 4(2.8,-2)
  silkscreen extent -3.25,-3.25 3.25,3.25, body extent -3.4,-3.25 3.4,3.25, height 4.3
TP_SMD_1MM [mm]
  round 1 smd paste-10 mask+0.05: 1(0,0)
  silkscreen extent -0.7,-0.7 0.7,0.7

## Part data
B1: library part MCD-01800, "Switch HW BLUE High4.3mm 2.25 Newtons, BEND type", Manufacturer=C&K, Manufacturer_Part_Number=KSC721JLFS
B2: library part MCD-01799, "Switch HW BLACK High3.5mm 2Newtons, BEND type", Manufacturer=C&K, Manufacturer_Part_Number=KSC321JLFS
C1 C2 C3 C9 C12 C13 C16 C17 C19 C21 C24 C26 C28 C29 C37 C38 C40 C43: library part MCD-00006, "Capacitor, MLCC, 100nF, 16V, X7R, +/-10%, 0402, T=0.5mm", Alternate_Manufacturer=MURATA, Alternate_Manufacturer_Part_Number=GCM155R71C104KA55D, Manufacturer=YAGEO, Manufacturer_Part_Number=CC0402KRX7R7BB104, Package=0402
C4 C10: library part MCD-00015, "Capacitor, MLCC, 10pF, 50V, NPO, +/-5%, 0402, T=0.5mm", Alternate_Manufacturer=MURATA, Alternate_Manufacturer_Part_Number=GCM155R71C104KA55D, Manufacturer=YAGEO, Manufacturer_Part_Number=CC0402JRNPO9BN100, Package=0402
C5: library part MCD-00099, "Capacitor, MLCC, 10uF, 10V, X5R, +/-10%, 0603, T=0.8mm", Manufacturer=MURATA, Manufacturer_Part_Number=GRM188R61A106KE69D, Package=0603
C6: library part MCD-01099, "Capacitor, MLCC, 100nF, 50V, X7R, +/-10%, 0603, T=0.8mm", Alternate_Manufacturer=MURATA, Alternate_Manufacturer_Part_Number=GCM155R71C104KA55D, Manufacturer=YAGEO, Manufacturer_Part_Number=CC0603KRX7R9BB104, Package=0603
C7: library part MCD-00205, "Capacitor, MLCC, 100pF, 50V, NPO, +/-5%, 0402, T=0.5mm", Alternate_Manufacturer=MURATA, Alternate_Manufacturer_Part_Number=GCM155R71C104KA55D, Manufacturer=YAGEO, Manufacturer_Part_Number=CC0402JRNPO9BN101, Package=0402
C11: library part MCD-00016, "Capacitor, MLCC, 20pF, 50V, NPO, +/- 5%, 0402, T=0.5mm", Alternate_Manufacturer=MURATA, Alternate_Manufacturer_Part_Number=GCM155R71C104KA55D, Manufacturer=YAGEO, Manufacturer_Part_Number=CC0402JRNPO9BN200, Package=0402
C14: library part MCD-02198, "Capacitor, MLCC, 10nF, 50V, X7R, +/-10%, 0402, T=0.5mm", Alternate_Manufacturer=MURATA, Alternate_Manufacturer_Part_Number=GCM155R71C104KA55D, Manufacturer=YAGEO, Manufacturer_Part_Number=CC0402KRX7R9BB103, Package=0402
C15 C18 C20 C23 C31 C39: library part MCD-00010, "Capacitor, MLCC, 1uF, 16V, X5R, +/-10%, 0603, T=0.8mm", Alternate_Manufacturer=MURATA, Alternate_Manufacturer_Part_Number=GCM155R71C104KA55D, Manufacturer=YAGEO, Manufacturer_Part_Number=CC0603KRX5R7BB105, Package=0603
C22 C25: library part MCD-00014, "Capacitor, MLCC, 10uF, 25V, X5R, +/-10%, 0805, T=0.85mm", Alternate_Manufacturer=MURATA, Alternate_Manufacturer_Part_Number=GCM155R71C104KA55D, Manufacturer=YAGEO, Manufacturer_Part_Number=CC0805KRX5R8BB106, Package=0805
C27 C41: library part MCD-01721, "Capacitor, MLCC, 4.7uF, 10V, X5R, +/-10%, 0603, T=0.8mm", Manufacturer=YAGEO, Manufacturer_Part_Number=CC0603KRX5R6BB475, Package=0603
C30: library part MCD-00006, "Capacitor, MLCC, 100nF, 16V, X7R, +/-10%, 0402, T=0.5mm", Manufacturer=YAGEO, Manufacturer_Part_Number=CC0402KRX7R7BB104, Package=0402
C32 C34: library part MCD-01932, "Capacitor, MLCC, 8.2pF, 50V, NPO, +/-0.25pF, 0402, T=0.5mm", Alternate_Manufacturer=MURATA, Alternate_Manufacturer_Part_Number=GCM155R71C104KA55D, Manufacturer=YAGEO, Manufacturer_Part_Number=CC0402CRNPO9BN8R2, Package=0402
C33 C42: library part MCD-02606, "Capacitor, MLCC, 2.2uF, 6.3V, X5R, +/-10%, 0402, T=0.5mm", Manufacturer=YAGEO, Manufacturer_Part_Number=CC0402KRX5R5BB225, Package=0402
C35 C36: library part MCD-00015, "Capacitor, MLCC, 10pF, 50V, NPO, +/-5%, 0402, T=0.5mm", Manufacturer=YAGEO, Manufacturer_Part_Number=CC0402JRNPO9BN100, Package=0402
CN1: library part MCD-03232, "USB_TypeC, 24 pins, RA, SMD, T=2.96mm (USB Certified 3.1)", Manufacturer="AMPHENOL ICC", Manufacturer_Part_Number=12401826E412A
CN3: library part MCD-00029, "Header, 4x1, 2.54mm, VR, TH, T=5.84mm/2.54mm", Manufacturer=SAMTEC, Manufacturer_Part_Number=TSW-104-07-G-S
CN4: library part MCD-01226, "Header, 5x2, 1.27mm, VR, SMD, T=5.97mm/3.05mm", Manufacturer=SAMTEC, Manufacturer_Part_Number=FTSH-105-01-L-DV-K
CN5: library part MCD-02080, "Socket, 10x1, 2.54mm, VR, TH, T=8.51/2.64mm", Manufacturer=SAMTEC, Manufacturer_Part_Number=SSW-110-01-G-S
CN6 CN9: library part MCD-01743, "Socket, 8x1, 2.54mm, VR, TH, T=8.51/2.64mm", Manufacturer=SAMTEC, Manufacturer_Part_Number=SSW-108-01-G-S
CN7 CN10: library part MCD-00213, "Header, 19x2, 2.54mm, VR, TH, T=5.84mm/10.16mm", Manufacturer=SAMTEC, Manufacturer_Part_Number=TSW-119-09-G-D
CN8: library part MCD-02079, "Socket, 6x1, 2.54mm, VR, TH, T=8.51/2.64mm", Manufacturer=SAMTEC, Manufacturer_Part_Number=SSW-106-01-G-S
D1 D2: library part MCD-00034, Manufacturer=STMICROELECTRONICS, Manufacturer_HQ_COO=EU
HW1: library part MCD-00547, "Sticker product 25x9 mm", Manufacturer=N/A
HW2: library part MCD-00235, "Sticker Board 25x9 mm", Manufacturer=N/A
JP1: library part MCD-00045, "Header, 2x1, 2.54mm, VR, TH, T=5.84mm/2.54mm", Manufacturer=SAMTEC, Manufacturer_Part_Number=TSW-102-07-G-S
JP2 JP3: library part MCD-00214, "Header, 2x1, 2,54mm, VR, TH, Height 5.84mm/10.16mm", Manufacturer=SAMTEC, Manufacturer_Part_Number=TSW-102-09-G-S
JP4: library part MCD-00686, "Header, 4x2, 2.54mm, VR, TH, T=5.84mm/2.54mm", Manufacturer=SAMTEC, Manufacturer_Part_Number=TSW-104-07-G-D
JP5 JP6 JP7 JP8 JP9 JP10 JP11: library part MCD-00683, "Header, 2x1, 2.54mm, VR, TH, T=5.84mm/2.54mm", Alternate_Manufacturer=LIANYI, Alternate_Manufacturer_Part_Number=313102S111116, Manufacturer=SAMTEC, Manufacturer_Part_Number=TSW-102-07-G-S
LD1: library part MCD-02631, "LED Bicolor, Green/Red, 2V, 20mA,  4-PLCC", Manufacturer="WURTH ELEKTRONIK", Manufacturer_Part_Number=150141SV73110, Package=4-PLCC
LD2: library part MCD-00708, "LED 0402 Red", Alternate_Manufacturer="OSRAM OPTO SEMICONDUCTORS", Alternate_Manufacturer_Part_Number="LS Q976-NR-1", Manufacturer=KINGBRIGHT, Manufacturer_Part_Number=KPHHS-1005SURCK, Package="LED 0402"
LD3 LD4: library part MCD-02330, "LED, Yellow Green, 2V, 25mA, 0402, 0.45mm", Alternate_Manufacturer="OSRAM OPTO SEMICONDUCTORS", Alternate_Manufacturer_Part_Number="LG Q396-PS-35", Manufacturer=EVERLIGHT, Manufacturer_Part_Number=16-213SYGC/S530-E3/TR8, Package=0402
R1 R13 R26: library part MCD-00061, "Resistor, 1K, 0402, +/-1%,1/16W", Alternate_Manufacturer=YAGEO, Alternate_Manufacturer_Part_Number=RT0402FRE07100KL, Manufacturer_Part_Number=RC0402FR-071KL, Package=0402
R2: library part MCD-00062, "Resistor, 330R, 0402, +/-1%, 1/16W", Alternate_Manufacturer=YAGEO, Alternate_Manufacturer_Part_Number=RT0402FRE07100KL, Manufacturer_Part_Number=RC0402FR-07330RL, Package=0402
R3 R6 R12: library part MCD-00333, "Resistor, 5K1, 0402, +/-1%, 1/16W", Alternate_Manufacturer=YAGEO, Alternate_Manufacturer_Part_Number=RT0402FRE07100KL, Manufacturer_Part_Number=RC0402FR-075K1L, Package=0402
R4 R11 R14: library part MCD-00059, "Resistor, 100K, 0402, +/-1%, 1/16W", Alternate_Manufacturer=YAGEO, Alternate_Manufacturer_Part_Number=RT0402FRE07100KL, Manufacturer_Part_Number=RC0402FR-07100KL, Package=0402
R5 R7 R8 R18 R21 R22: library part MCD-00053, "Resistor, 10K, 0402, +/-1%, 1/16W", Alternate_Manufacturer=YAGEO, Alternate_Manufacturer_Part_Number=RT0402FRE07100KL, Manufacturer_Part_Number=RC0402FR-0710KL, Package=0402
R9: library part MCD-00413, "Resistor, 180K, 0402, +/-1%, 1/16W", Manufacturer=YAGEO, Manufacturer_Part_Number=RC0402FR-07180KL, Package=0402
R10: library part MCD-00513, "Resistor, 680K, 0402, +/-1%, 1/16W", Alternate_Manufacturer=YAGEO, Alternate_Manufacturer_Part_Number=RT0402FRE07100KL, Manufacturer_Part_Number=RC0402FR-07680KL, Package=0402
R15 R17 R20: library part MCD-00067, "Resistor, 100R, 0402, +/- 1%, 1/16W", Alternate_Manufacturer=YAGEO, Alternate_Manufacturer_Part_Number=RT0402FRE07100KL, Manufacturer_Part_Number=RC0402FR-07100RL, Package=0402
R16: library part MCD-00068, "Resistor, 1K5, 0402, +/-1%, 1/16W", Alternate_Manufacturer=YAGEO, Alternate_Manufacturer_Part_Number=RT0402FRE07100KL, Manufacturer_Part_Number=RC0402FR-071K5L, Package=0402
R19: library part MCD-00069, "Resistor, 36K, 0402, +/-1%, 1/16W", Alternate_Manufacturer=YAGEO, Alternate_Manufacturer_Part_Number=RT0402FRE07100KL, Manufacturer_Part_Number=RC0402FR-0736KL, Package=0402
R23: library part MCD-00455, "Resistor, 33R, 0402, +/-1%, 1/16W", Alternate_Manufacturer=YAGEO, Alternate_Manufacturer_Part_Number=RT0402FRE07100KL, Manufacturer_Part_Number=RC0402FR-0733RL, Package=0402
R24 R34 R35 R36 R37: library part MCD-00052, "Resistor, 0R, 0402, +/-5%, 1/16W", Alternate_Manufacturer=YAGEO, Alternate_Manufacturer_Part_Number=RT0402FRE07100KL, Manufacturer_Part_Number=RC0402JR-070RL, Package=0402
R25: library part MCD-00063, "Resistor, 47K, 0402, +/-1%, 1/16W", Manufacturer=YAGEO, Manufacturer_Part_Number=RC0402FR-0747KL, Package=0402
R27: library part MCD-01943, "Resistor, 15K, 0402, +/-1%, 1/16W", Manufacturer=YAGEO, Manufacturer_Part_Number=RC0402FR-0715KL, Package=0402
R28 R30: library part MCD-00507, "Resistor, 680R, 0402, +/-1%, 1/16W", Alternate_Manufacturer=YAGEO, Alternate_Manufacturer_Part_Number=RT0402FRE07100KL, Manufacturer_Part_Number=RC0402FR-07680RL, Package=0402
R29: library part MCD-00182, "Resistor, 1M, 0402, +/-1%, 1/16W", Alternate_Manufacturer=YAGEO, Alternate_Manufacturer_Part_Number=RT0402FRE07100KL, Manufacturer_Part_Number=RC0402FR-071ML, Package=0402
R31: library part MCD-00059, "Resistor, 100K, 0402, +/-1%, 1/16W", Manufacturer=YAGEO, Manufacturer_Part_Number=RC0402FR-07100KL, Package=0402
R32: library part MCD-00333, "Resistor, 5K1, 0402, +/-1%, 1/16W", Manufacturer=YAGEO, Manufacturer_Part_Number=RC0402FR-075K1L, Package=0402
R33: library part MCD-00067, "Resistor, 100R, 0402, +/- 1%, 1/16W", Manufacturer=YAGEO, Manufacturer_Part_Number=RC0402FR-07100RL, Package=0402
R38: library part MCD-00056, "Resistor, 0R, 0603, +/-5%, 1/10W", Manufacturer=YAGEO, Manufacturer_Part_Number=RC0603JR-070RL, Package=0603
SB1 SB2 SB3 SB4 SB5 SB6 SB7 SB9 SB12 SB14 SB18 SB20 SB25 SB27 SB28 SB29 SB30 SB31 SB35 SB36 SB37 SB39 SB40 SB43 SB46 SB52 SB54: library part MCD-00071, "Solder Bridge ON", Manufacturer=YAGEO, Manufacturer_Part_Number=RC0603JR-070RL, Package=SB0603
SB8 SB10 SB11 SB13 SB15 SB16 SB17 SB19 SB21 SB22 SB23 SB24 SB26 SB32 SB33 SB34 SB38 SB41 SB42 SB44 SB45 SB47 SB48 SB49 SB50 SB51 SB53: library part MCD-00072, "Solder Bridge OFF", Manufacturer=YAGEO, Manufacturer_Part_Number=RC0603JR-070RL, Package=SB0603
T1: library part MCD-00073, "NPN Bipolar Transistor", Manufacturer="ON SEMICONDUCTOR", Manufacturer_Part_Number=BSR14, Package=SOT23
T2: library part MCD-01969, "Transistor, N-channel enhancement mode field-effect transistor", Manufacturer=NEXPERIA, Manufacturer_Part_Number=BSN20BK
TP1 TP2 TP3: library part MCD-00074, "Test Point 1mm", Manufacturer=N/A
U1: library part MCD-03056, "Medium-density performance line ARM-based 32-bit MCU with 128KB Flash", Manufacturer=STMICROELECTRONICS, Manufacturer_Part_Number=STM32F103CBT6, Package=LQFP48
U2: library part MCD-00163, "Very low capacitance ESD protection", Manufacturer=STMICROELECTRONICS, Manufacturer_HQ_COO=EU
U3: library part MCD-00083, "Enhanced single channel power switches with active low enable pin", Manufacturer=STMICROELECTRONICS, Manufacturer_HQ_COO=EU
U4: library part MCD-01207, "High power Transient voltage suppressor:25V/35A EOS and ESD transients protection.", Manufacturer=STMICROELECTRONICS, Manufacturer_HQ_COO=EU, Manufacturer_Part_Number=ESDA25P35-1U1M, Package=QFN1610
U5: library part MCD-03166, "28 V / 5 A Rated OVP with Low On-resistance and Integrated TVS", Manufacturer=ON_SEMICONDUCTOR, Package=WLCSP-12
U6 U7: library part MCD-00136, "Dual Transil array for ESD protection", Manufacturer=STMICROELECTRONICS, Manufacturer_HQ_COO=EU
U8: library part MCD-00663, "200 mA low quiescent current very low noise LDO", Manufacturer=STMICROELECTRONICS, Manufacturer_HQ_COO=EU, Package=SOT23-5L
U9 U10: library part MCD-00170, "ESD protection 6V1", Manufacturer=STMICROELECTRONICS, Manufacturer_HQ_COO=EU, Manufacturer_Part_Number=ESDALC6V1-1U2
U11: library part MCD-00088, "IC REG LDO 5V 0.8A SOT223", Manufacturer=STMICROELECTRONICS, Manufacturer_HQ_COO=EU, Package=SOT-223
U12: library part MCD-03339, "LDO, output 1.5 to 5.5V 1A adjustable", Manufacturer=STMICROELECTRONICS, Package="DFN6 3x3mm"
U13: library part MCD-03252, "MCU, ARM Cortex-M0+ 32-bit, 256K Flash, 20KB RAM, With Crypto", Manufacturer=STMICROELECTRONICS, Manufacturer_Part_Number=STM32U083RCT6, Package=LQFP64
X1 X3: library part MCD-00092, "Crystal, 8MHz, 8pF, +/-20ppm, 500R, 3.2x2.5mm", Manufacturer=NDK, Manufacturer_Part_Number=NX3225GD-8MHZ-EXS00A-CG04874, Package=3.2x2.5mm
X2: library part MCD-01479, "Crystal, 32.768kHz, 6pF, +/-20ppm, 80K, 2.05x1.2mm", Manufacturer=NDK, Manufacturer_Part_Number=NX2012SA-32.768KHZ-EXS00A-MU00527, Package=2.05x1.2mm

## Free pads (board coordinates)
  round 3.2 hole 3.2 unplated: 0(-59.13,54.57) 0(-26.11,2.5) 0(-10.87,53.3)
  oval 0.8x1.4 on Top Paste mask+0.05: 0(-27.39,79.831) 0(-27.03,76.381) 0(-18.77,76.381) 0(-18.41,79.831)
  round 0.508 on Mech16: 1(-62.209,-20.469) 1(-13.362,-20.469)
  round 0.3 on Mech1 mask+0.05: 2(0,0) 3(-70,0) 4(-70,82.5) 5(0,82.5)

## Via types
v1: diameter 0.45, hole 0.25, Top Layer to Bottom Layer, tented both sides, 618 vias
v2: diameter 0.7, hole 0.4, Top Layer to Bottom Layer, tented both sides, 28 vias
v3: diameter 0.5, hole 0.3, Top Layer to Bottom Layer, tented both sides, 3 vias

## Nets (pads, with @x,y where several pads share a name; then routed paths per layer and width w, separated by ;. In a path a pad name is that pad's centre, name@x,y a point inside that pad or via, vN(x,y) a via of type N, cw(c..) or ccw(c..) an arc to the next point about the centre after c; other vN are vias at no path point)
3V3: CN4.3 CN6.2 CN6.4 CN7.12 CN7.16 JP5.2 JP10.1 R28.2 SB1.2 U7.4 | length 101.8
  Top Layer w0.3: JP5.2@-32.258,43.008 -29.298,43.008 R28.2@-28.742,42.452
  Top Layer w0.4: v1(-68.646,67.999) CN4.3@-66.938,67.999 ; v2(-60.824,40.285) -60.824,34.674 CN6.4@-59.13,32.98 ; -60.753,38.06 CN6.2@-59.13,38.06 ; U7.4@-57.738,61.684 -57.901,61.684 -58.575,61.01 v2(-58.575,59.81) -58.575,57.958 -57.675,57.057 -57.672,57.057 -56.012,55.397 v2(-56.012,48.89) ; v2(-47.738,48.891) -33.202,48.891 -32.258,47.947 JP5.2@-32.258,43.008
  Bottom Layer w0.4: v1(-68.646,67.999) -68.17,67.522 -59.985,67.522 -58.575,66.113 v2(-58.575,59.81) -58.535,59.77 -55.118,59.77 JP10.1@-54.455,60.432 -54.253,60.432 JP10.1@-54.855,59.83 ; CN7.16@-64.21,32.98 CN6.4@-59.13,32.98 ; CN7.12@-64.21,38.06 CN6.2@-59.13,38.06 ; v2(-60.824,40.285) -60.824,44.078 v2(-56.012,48.89) v2(-47.738,48.891)
3V3_STLK: C1.1 C2.1 C3.1 C15.2 C16.2 C17.1 CN3.1 LD1.4 T1.3 U1.1 U1.9 U1.24 U1.36 U1.48 U8.5 | length 91.7
  Top Layer w0.3: U1.9@-41.993,66.33 -41.971,66.352 -40.828,66.352 -40.525,66.655 -37.384,66.655 -37.378,66.66 v1(-36.45,66.66) ; U1.48@-40.493,71.83 C1.1@-40.493,74.172 ; C17.1@-34.993,61.575 U1.24@-34.993,63.33 ; U1.36@-33.493,70.33 C3.1@-31.668,70.33 ; T1.3@-27.484,65.416 -27.403,65.334 v1(-27.403,64.193) ; C15.2@-27.452,61.605 -27.421,61.636 v1(-27.421,62.238) -27.106,62.553 v1(-20.42,62.553) ; v1(-9.505,73.273) -9.108,73.273 -8.85,73.53 LD1.4@-8.85,74.66
  Top Layer w0.4: U1.1@-42.259,70.401 C2.1@-42.259,74.216 ; C2.1@-42.259,74.222 C2.1@-42.259,74.216 ; CN3.1@-40.022,79.63 -39.928,79.536 v1(-39.928,74.216) -40.588,74.216 C2.1@-42.259,74.216 ; v1(-36.454,61.567) C15.2@-27.42,61.567 ; C3.1@-31.572,70.385 v1(-31.572,71.058) ; C15.2@-27.452,61.605 -27.42,61.573 U8.5@-24.973,61.573
  Bottom Layer w0.152: -36.752,74.083 -36.463,73.795 -36.454,73.804 -36.174,74.083
  Bottom Layer w0.3: v1(-27.421,62.238) v1@-27.421,64.193 ; v1(-20.42,62.553) -20.42,63.321 -18.056,65.685 -10.405,65.685 -9.505,66.585 v1(-9.505,73.273)
  Bottom Layer w0.4: v1(-39.928,74.216) -33.823,74.216 -31.572,71.966 v1(-31.572,71.058) ; v1(-36.454,61.567) -36.454,73.804 -36.454,74.212
5V: C23.2 C24.2 CN6.5 CN7.18 D2.1 JP4.2 JP4.4 JP4.6 JP4.8 R6.2 R30.1 U12.1 U12.6 | length 176.9
  Top Layer w0.3: v1(-50.276,38.09) -49.806,38.09 R30.1@-49.776,38.06 ; -50.276,47.88 v2(-48.513,49.642) ; v1(-50.275,42.707) -50.275,47.879 ; v1(-36.015,76.703) -36.015,75.173 -36.031,75.157 R6.2@-35.991,75.116 ; U12.6@-25.78,45.088 -25.78,44.311 -25.457,43.988 -23.529,43.988 -23.18,44.338 U12.1@-23.18,45.088 ; v1(-16.214,81.095) -1.965,81.095 -1.005,80.135 -1.005,62.304 -3.659,59.65 JP4.2@-5.79,59.65
  Top Layer w0.4: CN7.18@-64.21,30.44 -62.496,32.154 v2(-62.496,40.28) ; v2(-48.513,49.642) -19.28,49.642 ; U12.1@-23.18,45.088 C23.2@-21.023,45.088 ; C23.2@-21.018,45.093 -20.754,45.093 -19.272,46.575 -19.272,50.981 -13.41,56.843 JP4.8@-13.41,59.65
  Top Layer w0.5: D2.1@-16.404,59.65 JP4.8@-13.41,59.65 JP4.2@-5.79,59.65
  Bottom Layer w0.3: v1(-50.276,38.09) v1(-50.275,42.707) ; v1(-36.015,76.703) -30.52,76.703 -29.415,77.807 -29.415,80.73 -28.815,81.33 -16.449,81.33 v1(-16.214,81.095)
  Bottom Layer w0.4: CN7.18@-64.21,30.44 CN6.5@-59.13,30.44 ; v2(-62.496,40.28) -62.496,43.505 -56.359,49.642 v2(-48.513,49.642)
5V_STLK: C12.2 JP4.1 U3.1 | length 6.5
  Top Layer w0.381: U3.1@-5.791,68.656 C12.2@-5.791,67.158 -5.791,62.191 JP4.1@-5.79,62.19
